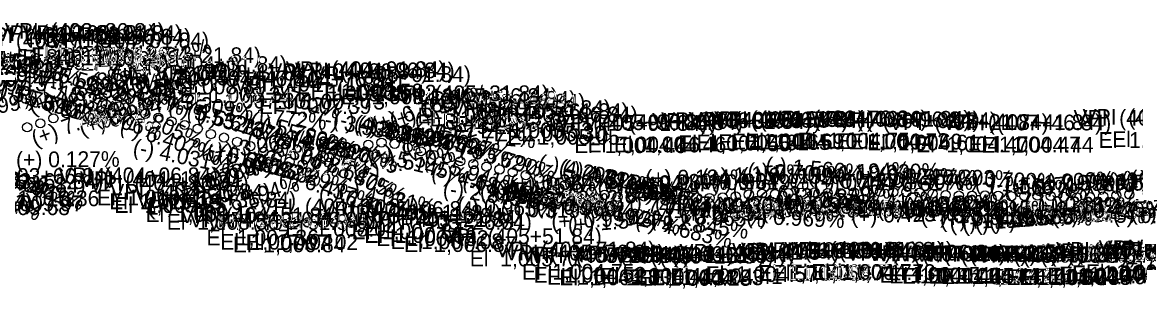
# Model space of a CAD drawing. Extents: x 16972137 to 16976737, y 12558490 to 12559551.
# Drawn here: x 16974747.9 to 16975172.2, y 12558926.1 to 12559027.7 of the extents above; entities that cross this region are included whole.
import ezdxf

# ---------------------------------------------------------------- set-up
doc = ezdxf.new("R2010")
doc.units = 0
doc.layers.add('RD_DDB_GradeTX', color=7, linetype='Continuous')
doc.layers.add('RD_DDB_PI', color=7, linetype='Continuous')

msp = doc.modelspace()

# ---------------------------------------------------------------- linework, layer by layer
at = {"layer": 'RD_DDB_PI'}
for centre in [(16974769.74, 12558994.82), (16974774.74, 12558995.62), (16974779.74, 12558996.42), (16974784.74, 12558995.59), (16974789.74, 12558994.21), (16974754.74, 12558989.18), (16974759.74, 12558991.1), (16974764.74, 12558993.02), (16974794.74, 12558992.81), (16974799.74, 12558991.37), (16974804.74, 12558989.95), (16974749.74, 12558987.7), (16974809.74, 12558988.55), (16974814.74, 12558987.17), (16974819.74, 12558985.09), (16974824.74, 12558983.76), (16974829.74, 12558982.11), (16974879.74, 12558981.07), (16974884.74, 12558981.84), (16974889.74, 12558981.39), (16974834.74, 12558980.5), (16974839.74, 12558978.34), (16974869.74, 12558977.97), (16974874.74, 12558979.51), (16974894.74, 12558979.95), (16974899.74, 12558978.51), (16974904.74, 12558977.12), (16974844.74, 12558976.13), (16974849.74, 12558974.53), (16974854.74, 12558973.53), (16974859.74, 12558974.41), (16974864.74, 12558976.27), (16974909.74, 12558975.92), (16974914.74, 12558974.71), (16974919.74, 12558973.64), (16974924.74, 12558972.66), (16974929.74, 12558971.58), (16974934.74, 12558970.51), (16974939.74, 12558969.43), (16974944.74, 12558968.14), (16974949.74, 12558966.98), (16974954.74, 12558965.82), (16974959.74, 12558964.56), (16974964.74, 12558963.08), (16974969.74, 12558961.91), (16974974.74, 12558961.19), (16974979.74, 12558960.95), (16974984.74, 12558961.32), (16974989.74, 12558961.61), (16974994.74, 12558961.53), (16974999.74, 12558961.63), (16975004.74, 12558960.97), (16975009.74, 12558960.73), (16975014.74, 12558960.98), (16975019.74, 12558961.36), (16975024.74, 12558962.07), (16975029.74, 12558962.37), (16975034.74, 12558962.19), (16975039.74, 12558962.54), (16975044.74, 12558962.77), (16975049.74, 12558962.8), (16975054.74, 12558962.62), (16975059.74, 12558962.64), (16975064.74, 12558962.85), (16975069.74, 12558963.07), (16975074.74, 12558963), (16975079.74, 12558962.95), (16975084.74, 12558962.92), (16975089.74, 12558962.74), (16975094.74, 12558962.35), (16975099.74, 12558961.88), (16975104.74, 12558961.64), (16975109.74, 12558961.56), (16975114.74, 12558961.68), (16975119.74, 12558961.53), (16975124.74, 12558961.39), (16975129.74, 12558961.5), (16975134.74, 12558961.65), (16975139.74, 12558961.51), (16975144.74, 12558961.16), (16975149.74, 12558961), (16975154.74, 12558961.08), (16975159.74, 12558961.31), (16975164.74, 12558961.66), (16975169.74, 12558962.07)]:
    msp.add_circle(centre, 1.75, dxfattribs=at)

# ---------------------------------------------------------------- texts
at = {"layer": 'RD_DDB_GradeTX'}
for s, rotation, p in [('(-) 5.532%', 344.5396, (16974726.19, 12559014.9)), ('(+) 7.173%', 19.7305, (16974783.44, 12559002.92)), ('(-) 5.613%', 344.3231, (16974733.31, 12559013.16)), ('(-) 3.309%', 350.6045, (16974719.65, 12559009.41)), ('(-) 5.522%', 344.5648, (16974751.23, 12559007.81)), ('(-) 8.647%', 336.6189, (16974780.84, 12559007.07)), ('(+) 3.220%', 9.1473, (16974787.26, 12559000.68)), ('(+) 3.199%', 9.0882, (16974794.6, 12559001.84)), ('(+) 7.308%', 20.0734, (16974751.55, 12558992.47)), ('(+) 6.308%', 17.5064, (16974756.79, 12558993.48)), ('(-) 5.329%', 345.0802, (16974761.22, 12559003.79)), ('(+) 4.640%', 13.0615, (16974762.91, 12558993.83)), ('(-) 6.437%', 342.1594, (16974773.06, 12559003.5)), ('(+) 7.705%', 21.07, (16974781.14, 12558989.7)), ('(-) 5.737%', 343.9957, (16974733.98, 12559000.87)), ('(-) 5.690%', 344.1187, (16974738.91, 12558999.32)), ('(-) 8.306%', 337.4469, (16974755.17, 12559002.16)), ('(+) 7.654%', 20.9421, (16974776.09, 12558987.72)), ('(-) 5.762%', 343.9296, (16974832.2, 12559001.09)), ('(+) 6.194%', 17.2079, (16974888.92, 12558987.04)), ('(+) 3.199%', 9.0882, (16974715.67, 12558989.21)), ('(-) 5.615%', 344.3167, (16974745.24, 12558997.31)), ('(-) 6.606%', 341.7206, (16974764.58, 12558994.15)), ('(+) 5.954%', 16.5775, (16974770.52, 12558984.49)), ('(-) 8.805%', 336.2393, (16974780.6, 12558994.54)), ('(-) 3.309%', 350.6045, (16974798.51, 12558996.36)), ('(+) 6.788%', 18.7474, (16974882.16, 12558985.35)), ('(+) 7.491%', 20.5323, (16974752.73, 12558980.26)), ('(-) 5.532%', 344.5396, (16974803.11, 12558993.63)), ('(-) 5.613%', 344.3231, (16974810.15, 12558991.6)), ('(-) 5.737%', 343.9957, (16974814, 12558990.41)), ('(-) 1.772%', 354.938, (16974826.26, 12558990.03)), ('(+) 3.068%', 8.7226, (16974897.89, 12558986.89)), ('(-) 6.407%', 342.2362, (16974784.64, 12558985.94)), ('(-) 5.790%', 343.854, (16974834.12, 12558988.13)), ('(-) 5.536%', 344.5286, (16974838.33, 12558986.17)), ('(-) 3.938%', 348.8596, (16974860.1, 12558988.45)), ('(-) 4.299%', 347.8682, (16974865.96, 12558988.36)), ('(-) 4.311%', 347.8348, (16974873.91, 12558986.69)), ('(-) 4.323%', 347.8021, (16974875.17, 12558986.45)), ('(+) 7.422%', 20.3594, (16974880.63, 12558972.56)), ('(+) 6.223%', 17.2824, (16974894.93, 12558976.37)), ('(-) 8.306%', 337.4469, (16974833.27, 12558982.72)), ('(-) 4.823%', 346.442, (16974843.06, 12558982.74)), ('(-) 4.810%', 346.4763, (16974850.19, 12558980.98)), ('(-) 4.627%', 346.9751, (16974886.4, 12558984.71)), ('(-) 4.659%', 346.8864, (16974891.37, 12558983.66)), ('(-) 5.027%', 345.8922, (16974896.4, 12558983.57)), ('(-) 1.772%', 354.938, (16974905.93, 12558982.97)), ('(-) 4.031%', 348.6043, (16974789.71, 12558977.45)), ('(-) 5.690%', 344.1187, (16974815.66, 12558977.49)), ('(+) 3.068%', 8.7226, (16974818.87, 12558974.77)), ('(-) 6.606%', 341.7206, (16974844.06, 12558980.54)), ('(-) 4.277%', 347.9279, (16974853.78, 12558978.55)), ('(-) 5.762%', 343.9296, (16974908.88, 12558979)), ('(-) 5.790%', 343.854, (16974914.11, 12558977.47)), ('(+) 0.127%', 0.3642, (16974745.51, 12558972.36)), ('(+) 6.223%', 17.2824, (16974815.21, 12558964.13)), ('(-) 5.615%', 344.3167, (16974822.08, 12558975.74)), ('(-) 5.522%', 344.5648, (16974824.97, 12558975.01)), ('(-) 8.647%', 336.6189, (16974853.86, 12558975.5)), ('(-) 8.805%', 336.2393, (16974858.23, 12558973.48)), ('(+) 3.550%', 10.0648, (16974874.49, 12558967.89)), ('(-) 5.145%', 345.5743, (16974880.06, 12558975.48)), ('(-) 5.941%', 343.4548, (16974900.61, 12558972.74)), ('(-) 11.243%', 330.6573, (16974716.68, 12558972.27)), ('(-) 7.074%', 340.5204, (16974725.32, 12558971.44)), ('(-) 7.041%', 340.6064, (16974731.62, 12558969.24)), ('(+) 7.422%', 20.3594, (16974801.76, 12558956.1)), ('(+) 6.788%', 18.7474, (16974806.67, 12558959.73)), ('(-) 5.329%', 345.0802, (16974835.27, 12558971.64)), ('(-) 4.683%', 346.8212, (16974903.37, 12558968.2)), ('(-) 4.299%', 347.8682, (16974944.06, 12558971.58)), ('(-) 4.311%', 347.8348, (16974952, 12558969.85)), ('(-) 4.323%', 347.8021, (16974953.25, 12558969.57)), ('(+) 1.157%', 3.311, (16975007.01, 12558965.61)), ('(-) 0.700%', 357.9941, (16975024.18, 12558968.04)), ('(-) 1.566%', 355.5233, (16975030.94, 12558970.36)), ('(+) 1.194%', 3.4171, (16975047.06, 12558966.41)), ('(+) 0.930%', 2.6636, (16975058.4, 12558966.41)), ('(-) 6.962%', 340.807, (16974734.83, 12558968.18)), ('(-) 6.437%', 342.1594, (16974845.29, 12558967.65)), ('(-) 5.536%', 344.5286, (16974915.25, 12558964.87)), ('(-) 4.823%', 346.442, (16974920.7, 12558964.02)), ('(+) 0.384%', 1.1002, (16974933.51, 12558963.35)), ('(-) 5.145%', 345.5743, (16974960.37, 12558967.22)), ('(+) 1.194%', 3.4171, (16974967.21, 12558961.64)), ('(-) 4.659%', 346.8864, (16974969.15, 12558965.54)), ('(-) 5.027%', 345.8922, (16974973.84, 12558964.11)), ('(+) 1.417%', 4.0537, (16974977.4, 12558961.13)), ('(+) 0.930%', 2.6636, (16974978.49, 12558962.69)), ('(+) 0.124%', 0.3549, (16974985.26, 12558965.4)), ('(+) 0.904%', 2.589, (16975003.91, 12558963.1)), ('(-) 0.319%', 359.0866, (16975010.26, 12558964.28)), ('(-) 0.115%', 359.6692, (16975021.94, 12558966.28)), ('(+) 0.477%', 1.3674, (16975049.39, 12558963.12)), ('(-) 0.744%', 357.8701, (16975049.37, 12558964.64)), ('(+) 0.124%', 0.3549, (16975065.25, 12558965.9)), ('(-) 0.740%', 357.881, (16975069.25, 12558965.08)), ('(+) 0.617%', 1.766, (16975070.74, 12558962.68)), ('(-) 0.557%', 358.4036, (16975073.91, 12558966.35)), ('(-) 0.303%', 359.1328, (16975088.19, 12558965.8)), ('(-) 0.700%', 357.9941, (16975104.13, 12558965.24)), ('(-) 1.566%', 355.5233, (16975110.68, 12558964.11)), ('(+) 1.719%', 4.9123, (16975122.43, 12558960.99)), ('(+) 1.200%', 3.4347, (16975125.09, 12558962.76)), ('(-) 0.598%', 358.2878, (16975133.82, 12558964.11)), ('(+) 1.406%', 4.0225, (16975145.57, 12558962.63)), ('(-) 0.557%', 358.4036, (16975153.87, 12558964.12)), ('(+) 1.251%', 3.5806, (16975156.63, 12558963.6)), ('(+) 1.139%', 3.2587, (16975161.8, 12558964.25)), ('(+) 1.105%', 3.1629, (16975166.86, 12558964.64)), ('(+) 1.006%', 2.8782, (16975170.44, 12558965.13)), ('(+) 3.550%', 10.0648, (16974795.8, 12558953.92)), ('(+) 6.194%', 17.2079, (16974816.27, 12558951.98)), ('(-) 6.407%', 342.2362, (16974860.59, 12558961.61)), ('(-) 4.031%', 348.6043, (16974868.03, 12558961.67)), ('(-) 2.845%', 351.9036, (16974907.89, 12558961.61)), ('(+) 1.471%', 4.2067, (16974922.41, 12558959.74)), ('(+) 1.157%', 3.311, (16974927.15, 12558960.99)), ('(-) 4.810%', 346.4763, (16974927.83, 12558962.31)), ('(-) 4.277%', 347.9279, (16974931.9, 12558961.84)), ('(-) 3.938%', 348.8596, (16974936.18, 12558961.23)), ('(-) 2.632%', 352.5034, (16974937.48, 12558960.74)), ('(+) 2.849%', 8.1075, (16974958.97, 12558955.74)), ('(-) 5.941%', 343.4548, (16974980.5, 12558961.52)), ('(-) 2.632%', 352.5034, (16975018.32, 12558962.21)), ('(+) 2.849%', 8.1075, (16975039.82, 12558955.13)), ('(-) 1.877%', 354.6387, (16975116.17, 12558963.35)), ('(-) 1.411%', 355.9634, (16975163.97, 12558962.81)), ('(-) 0.965%', 357.2376, (16974913.5, 12558955.14)), ('(-) 0.969%', 357.226, (16974943.73, 12558954.91)), ('(-) 0.744%', 357.8701, (16974968.98, 12558955.63)), ('(-) 0.740%', 357.881, (16974988.86, 12558956.05)), ('(+) 1.471%', 4.2067, (16975003.06, 12558953.64)), ('(-) 0.303%', 359.1328, (16975008.02, 12558955.01)), ('(+) 1.543%', 4.4116, (16975035.73, 12558953.57)), ('(-) 1.877%', 354.6387, (16975035.42, 12558958.88)), ('(-) 0.983%', 357.1871, (16975038.2, 12558955.9)), ('(+) 1.417%', 4.0537, (16975058.04, 12558954.81)), ('(+) 0.832%', 2.3829, (16975078.56, 12558954.42)), ('(-) 1.411%', 355.9634, (16975083.33, 12558956.47)), ('(+) 0.904%', 2.589, (16975084.36, 12558954.73)), ('(-) 0.313%', 359.1029, (16975129.67, 12558955.57)), ('(-) 0.312%', 359.107, (16975134.73, 12558955.49)), ('(-) 0.319%', 359.0866, (16974930.08, 12558953.56)), ('(-) 4.627%', 346.9751, (16974961.51, 12558955.02)), ('(-) 0.965%', 357.2376, (16974993.4, 12558951.28)), ('(+) 0.085%', 0.2447, (16974993.66, 12558953.36)), ('(+) 0.832%', 2.3829, (16974998.64, 12558951.09)), ('(-) 0.209%', 359.401, (16975013.53, 12558954.64)), ('(+) 0.384%', 1.1002, (16975013.73, 12558952.89)), ('(-) 0.969%', 357.226, (16975023.63, 12558951.04)), ('(+) 0.999%', 2.8602, (16975029.52, 12558952.7)), ('(-) 0.314%', 359.1012, (16975045.08, 12558953.57)), ('(-) 0.598%', 358.2878, (16975053.5, 12558954.5)), ('(-) 0.545%', 358.4399, (16975058.4, 12558954.2)), ('(+) 0.425%', 1.2186, (16975063.71, 12558951.09)), ('(+) 0.085%', 0.2447, (16975073.66, 12558953.7)), ('(-) 0.624%', 358.2125, (16975083.49, 12558954.07)), ('(+) 0.310%', 0.8881, (16975090.24, 12558951.08)), ('(-) 0.209%', 359.401, (16975093.52, 12558953.8)), ('(+) 0.911%', 2.6078, (16975097.64, 12558949.47)), ('(+) 1.409%', 4.0302, (16975101.42, 12558948.18)), ('(-) 0.115%', 359.6692, (16975101.87, 12558953.82)), ('(+) 1.639%', 4.6854, (16975106.28, 12558947.84)), ('(+) 1.652%', 4.7219, (16975111.11, 12558948.2)), ('(+) 1.665%', 4.758, (16975116.48, 12558948.6)), ('(-) 0.983%', 357.1871, (16975118.1, 12558951.97)), ('(-) 0.314%', 359.1012, (16975125.07, 12558952.32)), ('(+) 0.477%', 1.3674, (16975129.66, 12558953.03)), ('(-) 0.545%', 358.4399, (16975138.37, 12558952.02)), ('(+) 1.223%', 3.4983, (16975140.29, 12558950.82)), ('(+) 0.425%', 1.2186, (16975143.69, 12558952.79)), ('(+) 0.414%', 1.1859, (16975150.83, 12558953.91)), ('(+) 0.617%', 1.766, (16975151.07, 12558953.15)), ('(-) 0.624%', 358.2125, (16975163.45, 12558951.57)), ('(+) 0.310%', 0.8881, (16975170.23, 12558952.32)), ('(+) 0.999%', 2.8602, (16974949.62, 12558948.71)), ('(+) 1.543%', 4.4116, (16974955.98, 12558947.42)), ('(-) 4.683%', 346.8212, (16974981.13, 12558950)), ('(-) 2.845%', 351.9036, (16974987.05, 12558950.35))]:
    msp.add_text(s, height=6, rotation=rotation, dxfattribs=at).set_placement(p)
at = {"layer": 'RD_DDB_PI'}
for s, p in [('VPI  (403+76.84)', (16974731.5, 12559019.82)), ('VPI  (403+81.84)', (16974737.74, 12559020.62)), ('VPI  (403+86.84)', (16974741.21, 12559021.42)), ('VPI  (403+91.84)', (16974747.86, 12559020.59)), ('VPI  (403+96.84)', (16974751.33, 12559019.21)), ('VPI  (403+71.84)', (16974728.04, 12559018.02)), ('VPI  (404+01.84)', (16974758.16, 12559017.81)), ('VPI  (403+46.84)', (16974701.33, 12559009.96)), ('VPI  (403+51.84)', (16974707.63, 12559011.54)), ('El  1,011.10', (16974747.89, 12559011.32)), ('El  1,011.26', (16974751.12, 12559012.12)), ('El  1,011.42', (16974756.15, 12559012.92)), ('El  1,011.26', (16974761.12, 12559012.09)), ('El  1,010.98', (16974764.73, 12559010.71)), ('VPI  (404+21.84)', (16974777.92, 12559012.17)), ('VPI  (403+41.84)', (16974697.86, 12559008.13)), ('El  1,010.74', (16974740, 12559009.52)), ('El  1,010.70', (16974769.88, 12559009.31)), ('VPI  (404+31.84)', (16974787.86, 12559008.76)), ('VPI  (404+86.84)', (16974841.62, 12559006.07)), ('VPI  (404+91.84)', (16974848.27, 12559006.84)), ('VPI  (404+96.84)', (16974851.74, 12559006.39)), ('El  1,009.13', (16974714.44, 12559001.46)), ('El  1,009.44', (16974718.28, 12559003.04)), ('El  1,009.57', (16974788.23, 12559003.67)), ('VPI  (404+41.84)', (16974798.27, 12559005.5)), ('VPI  (404+46.84)', (16974801.74, 12559003.34)), ('VPI  (404+76.84)', (16974831.92, 12559002.97)), ('VPI  (405+01.84)', (16974857.92, 12559004.95)), ('El  1,008.76', (16974708.34, 12558999.63)), ('El  1,008.89', (16974798.05, 12559000.26)), ('VPI  (404+71.84)', (16974828.45, 12559001.27)), ('El  1,008.35', (16974852.55, 12558997.57)), ('El  1,008.50', (16974857.81, 12558998.34)), ('El  1,008.42', (16974862.84, 12558997.89)), ('VPI  (405+31.84)', (16974887.63, 12558997.66)), ('El  1,008.24', (16974807.81, 12558997)), ('El  1,007.80', (16974813.23, 12558994.84)), ('El  1,007.73', (16974843.26, 12558994.47)), ('El  1,008.13', (16974869.32, 12558996.45)), ('VPI  (405+36.84)', (16974891.09, 12558996.58)), ('VPI  (405+41.84)', (16974898.04, 12558995.51)), ('VPI  (405+46.84)', (16974901.5, 12558994.43)), ('El  1,007.39', (16974838.05, 12558992.77)), ('El  1,006.67', (16974898.46, 12558989.16)), ('VPI  (405+56.84)', (16974911.27, 12558991.98)), ('VPI  (405+61.84)', (16974918.04, 12558990.82)), ('VPI  (405+66.84)', (16974921.5, 12558989.56)), ('El  1,006.45', (16974903.08, 12558988.08)), ('El  1,006.24', (16974907.93, 12558987.01)), ('El  1,006.02', (16974912.84, 12558985.93)), ('VPI  (405+91.84)', (16974948.04, 12558986.32)), ('VPI  (405+96.84)', (16974951.5, 12558986.61)), ('VPI  (406+06.84)', (16974961.62, 12558986.63)), ('VPI  (406+31.84)', (16974987.86, 12558987.07)), ('VPI  (406+36.84)', (16974991.33, 12558987.37)), ('VPI  (406+46.84)', (16975001.74, 12558987.54)), ('VPI  (406+51.84)', (16975008.04, 12558987.77)), ('VPI  (406+56.84)', (16975011.5, 12558987.8)), ('VPI  (406+76.84)', (16975031.92, 12558988.07)), ('VPI  (406+91.84)', (16975048.27, 12558987.92)), ('VPI  (406+96.84)', (16975051.74, 12558987.74)), ('VPI  (407+01.84)', (16975058.33, 12558987.35)), ('VPI  (407+21.84)', (16975078.1, 12558986.68)), ('VPI  (407+41.84)', (16975098.45, 12558986.65)), ('VPI  (407+46.84)', (16975101.92, 12558986.51)), ('VPI  (407+91.84)', (16975148.45, 12558988.33)), ('VPI  (407+96.84)', (16975151.92, 12558988.63)), ('El  1,005.53', (16974922.43, 12558983.48)), ('El  1,005.30', (16974927.52, 12558982.32)), ('El  1,005.05', (16974932.72, 12558981.06)), ('El  1,004.40', (16974958.17, 12558977.82)), ('El  1,004.46', (16974963.28, 12558978.11)), ('El  1,004.46', (16974973.28, 12558978.13)), ('El  1,004.55', (16974997.84, 12558978.57)), ('El  1,004.61', (16975004.82, 12558978.87)), ('El  1,004.65', (16975013.08, 12558979.04)), ('El  1,004.69', (16975018.28, 12558979.27)), ('El  1,004.70', (16975023.34, 12558979.3)), ('El  1,004.75', (16975043.26, 12558979.57)), ('El  1,004.72', (16975058.14, 12558979.42)), ('El  1,004.69', (16975063.28, 12558979.24)), ('El  1,004.61', (16975069.82, 12558978.85)), ('El  1,004.47', (16975088.46, 12558978.18)), ('El  1,004.47', (16975108.46, 12558978.15)), ('El  1,004.44', (16975113.28, 12558978.01)), ('El  1,004.80', (16975158.05, 12558979.83)), ('El  1,004.86', (16975163.17, 12558980.13)), ('VPI  (403+61.84)', (16974717.86, 12558964.18)), ('VPI  (403+66.84)', (16974721.33, 12558966.1)), ('VPI  (404+06.84)', (16974761.62, 12558966.37)), ('VPI  (404+11.84)', (16974769.81, 12558964.95)), ('VPI  (404+16.84)', (16974773.27, 12558963.55)), ('VPI  (403+56.84)', (16974711.09, 12558962.7)), ('VPI  (404+26.84)', (16974781.39, 12558960.09)), ('VPI  (403+36.84)', (16974690.91, 12558956.26)), ('El  1,009.97', (16974728.46, 12558955.68)), ('El  1,010.36', (16974734.41, 12558957.6)), ('El  1,010.41', (16974776.36, 12558957.87)), ('El  1,010.13', (16974780.97, 12558956.45)), ('El  1,009.85', (16974782.96, 12558955.05)), ('VPI  (404+36.84)', (16974791.33, 12558957.11)), ('El  1,009.68', (16974723.2, 12558954.2)), ('El  1,009.16', (16974794.82, 12558951.59)), ('VPI  (404+51.84)', (16974808.04, 12558951.13)), ('VPI  (404+81.84)', (16974838.16, 12558954.51)), ('VPI  (405+06.84)', (16974861.39, 12558953.51)), ('VPI  (405+11.84)', (16974869.57, 12558952.12)), ('VPI  (405+16.84)', (16974873.04, 12558950.92)), ('El  1,008.56', (16974802.93, 12558948.61)), ('VPI  (404+56.84)', (16974811.5, 12558949.53)), ('VPI  (404+61.84)', (16974818.27, 12558948.53)), ('VPI  (404+66.84)', (16974821.74, 12558949.41)), ('VPI  (405+21.84)', (16974877.68, 12558949.71)), ('VPI  (405+26.84)', (16974881.15, 12558948.64)), ('El  1,007.36', (16974818.05, 12558942.63)), ('El  1,008.04', (16974848.05, 12558946.01)), ('El  1,007.84', (16974873.34, 12558945.01)), ('El  1,007.56', (16974878.23, 12558943.62)), ('El  1,007.32', (16974882.72, 12558942.42)), ('VPI  (405+51.84)', (16974907.8, 12558943.14)), ('El  1,007.04', (16974823.34, 12558941.03)), ('El  1,006.84', (16974828.17, 12558940.03)), ('El  1,007.02', (16974833.02, 12558940.91)), ('El  1,007.08', (16974888.26, 12558941.21)), ('El  1,006.87', (16974893.34, 12558940.14)), ('VPI  (405+71.84)', (16974928.22, 12558938.08)), ('VPI  (406+71.84)', (16975028.45, 12558937.85)), ('VPI  (406+81.84)', (16975038.16, 12558938)), ('VPI  (406+86.84)', (16975041.62, 12558937.95)), ('VPI  (407+86.84)', (16975141.8, 12558937.9)), ('VPI  (408+01.84)', (16975158.04, 12558938.55)), ('VPI  (408+06.84)', (16975161.5, 12558938.47)), ('VPI  (408+11.84)', (16975169.69, 12558938.78)), ('El  1,005.77', (16974918.4, 12558934.64)), ('VPI  (405+76.84)', (16974931.68, 12558936.91)), ('VPI  (405+81.84)', (16974937.92, 12558936.19)), ('VPI  (405+86.84)', (16974941.39, 12558935.95)), ('VPI  (406+01.84)', (16974958.16, 12558936.53)), ('VPI  (406+11.84)', (16974969.81, 12558935.97)), ('VPI  (406+16.84)', (16974973.27, 12558935.73)), ('VPI  (406+21.84)', (16974977.92, 12558935.98)), ('VPI  (406+26.84)', (16974981.39, 12558936.36)), ('VPI  (406+41.84)', (16974998.27, 12558937.19)), ('VPI  (406+61.84)', (16975018.27, 12558937.62)), ('VPI  (406+66.84)', (16975021.74, 12558937.64)), ('VPI  (407+06.84)', (16975061.8, 12558936.88)), ('VPI  (407+11.84)', (16975069.99, 12558936.64)), ('VPI  (407+16.84)', (16975073.45, 12558936.56)), ('VPI  (407+26.84)', (16975081.56, 12558936.53)), ('VPI  (407+31.84)', (16975088.04, 12558936.39)), ('VPI  (407+36.84)', (16975091.5, 12558936.5)), ('VPI  (407+51.84)', (16975108.22, 12558936.16)), ('VPI  (407+56.84)', (16975111.68, 12558936)), ('VPI  (407+61.84)', (16975118.45, 12558936.08)), ('VPI  (407+66.84)', (16975121.92, 12558936.31)), ('VPI  (407+71.84)', (16975128.63, 12558936.66)), ('VPI  (407+76.84)', (16975132.09, 12558937.07)), ('VPI  (407+81.84)', (16975138.33, 12558937.48)), ('El  1,004.75', (16974938.26, 12558929.58)), ('El  1,004.71', (16975040, 12558929.35)), ('El  1,004.74', (16975048.46, 12558929.5)), ('El  1,004.73', (16975053.08, 12558929.45)), ('El  1,004.72', (16975153.14, 12558929.4)), ('El  1,004.85', (16975167.96, 12558930.05)), ('El  1,004.52', (16974942.72, 12558928.41)), ('El  1,004.38', (16974947.78, 12558927.69)), ('El  1,004.33', (16974952.49, 12558927.45)), ('El  1,004.44', (16974968.28, 12558928.03)), ('El  1,004.33', (16974977.49, 12558927.47)), ('El  1,004.28', (16974982.84, 12558927.23)), ('El  1,004.33', (16974987.49, 12558927.48)), ('El  1,004.41', (16974994.82, 12558927.86)), ('El  1,004.57', (16975008.23, 12558928.69)), ('El  1,004.66', (16975028.28, 12558929.12)), ('El  1,004.67', (16975033.46, 12558929.14)), ('El  1,004.51', (16975074.58, 12558928.38)), ('El  1,004.46', (16975078.28, 12558928.14)), ('El  1,004.45', (16975083.08, 12558928.06)), ('El  1,004.44', (16975093.28, 12558928.03)), ('El  1,004.42', (16975097.96, 12558927.89)), ('El  1,004.44', (16975103.28, 12558928)), ('El  1,004.37', (16975118.05, 12558927.66)), ('El  1,004.34', (16975122.87, 12558927.5)), ('El  1,004.35', (16975127.66, 12558927.58)), ('El  1,004.40', (16975133.17, 12558927.81)), ('El  1,004.47', (16975138.46, 12558928.16)), ('El  1,004.55', (16975142.84, 12558928.57)), ('El  1,004.63', (16975147.9, 12558928.98))]:
    msp.add_text(s, height=6, dxfattribs=at).set_placement(p)

doc.saveas('drawing.dxf')
